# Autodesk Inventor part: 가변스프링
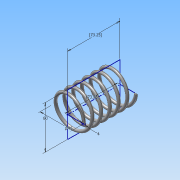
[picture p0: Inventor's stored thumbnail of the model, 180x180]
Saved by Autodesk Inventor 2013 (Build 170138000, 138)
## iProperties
Created: 2018-06
Part Number: 가변스프링
Material: 강철, 연강
Document SubType Name: Modeling
Designer: Administrator
Density: 7.86 g/cm^3
Mass: 82.8068 g
Surface Area: 106.473 cm^2
Volume: 10.5352 cm^3
Author: Administrator
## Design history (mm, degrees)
sketch "스케치1"
  geometry: L1 (0, 0)-(22.5, 0); L2 (0, 0)-(0, 73.25); L3 (0, 73.25)-(20.5, 73.25); C1 r 2 at (22.5, 0)
  constraints: 6 end point, 2 perpendicular, 1 centre point, 1 coincident, 1 horizontal
  dimensions: "d0" = 73.25 distance of L1.start L2.end (derived); "d2" = 45 diameter of C1.centre L2; "d3" = 4 diameter of C1
feature "코일2" sketch "스케치1" pitch "d13" = 10; turns "d15" = 6; dims "d14" = 73.25 (= d0), "d16" = 0, angle "d17" = 90 deg, angle "d18" = 90 deg, "d19" = 0, "d20" = 0
sketch "스케치3"
  geometry: L1 (0, 30)-(73.25, 30); L2 (73.25, 30)-(73.25, -30); L3 (73.25, -30)-(0, -30); L4 (0, -30)-(0, 30); 2 further points
  constraints: 8 end point, 2 parallel, 1 coincident, 1 horizontal, 1 midpoint, 1 perpendicular
  dimensions: "d21" = 73.25 distance of L1.start L1.end (derived); "d23" = 60 distance of L3.end L1.start
extrude "돌출1" sketch "스케치3" stored distance "d24" = 10; taper "d25" = 0 deg
node "솔리드2"
